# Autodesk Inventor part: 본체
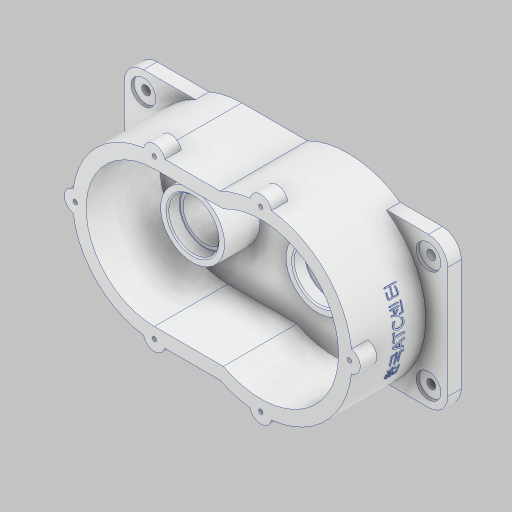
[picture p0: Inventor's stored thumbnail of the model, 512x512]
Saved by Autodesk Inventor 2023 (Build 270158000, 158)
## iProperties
Created: 2025-09
Part Number: 본체
Material: 알루미늄 6061
Document SubType Name: Modeling
Designer: home
Density: 2.7 g/cm^3
Appearance: 알루미늄 - 평지
Mass: 1574.72 g
Surface Area: 1310.46 cm^2
Volume: 583.229 cm^3
Author: home
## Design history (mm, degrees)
sketch "스케치1"
  geometry: L1 (118.5, -55)-(-118.5, -55); L2 (-118.5, -55)-(-118.5, 55); L3 (-118.5, 55)-(118.5, 55); L4 (118.5, 55)-(118.5, -55); L5 (118.5, -55)-(-118.5, 55); L6 (-118.5, -55)-(118.5, 55); 1 further point
  constraints: 12 end point, 2 midpoint, 2 parallel, 1 horizontal, 1 perpendicular
  dimensions: "d0" = 237 distance of L2.end L3.end; "d1" = 110 distance of L1.end L2.end
extrude "돌출1" new body sketch "스케치1" distance "d2" = 10; taper "d3" = 0 deg
fillet "모깎기1" dims "d4" = 14
sketch "스케치2"
  geometry: L1 (-118.5, 41)-(-118.5, -41) reference; L2 (118.5, -41)-(118.5, 41) reference; L3 (104.5, 55)-(-104.5, 55) reference; L4 (-104.5, -55)-(104.5, -55) reference; L5 (-42.5, 66.391)-(-42.5, -77.11); L6 (-118.5, 0)-(118.5, 0); L7 (35.5, 66.391)-(35.5, -81.26); L8 (-42.5, -50)-(8.132, -50); L9 (-42.5, 50)-(8.132, 50); L10 (-42.5, -60)-(5.684, -60); L11 (5.684, 60)-(-42.5, 60); A1 r 50 centre (-42.5, 0) between (-42.5, 50) and (-42.5, -50); A2 r 57 centre (35.5, 0) between (8.132, -50) and (8.132, 50); A3 r 67 centre (35.5, 0) between (5.684, -60) and (5.684, 60); A4 r 60 centre (-42.5, 0) between (-42.5, 60) and (-42.5, -60); 1 further point
  constraints: 14 end point, 8 point on circle, 5 point on line, 4 centre point, 2 midpoint, 2 parallel, 2 tangent, 2 vertical, 1 perpendicular, 3 other
  dimensions: "d5" = 76 distance from line of A1.centre L1; "d6" = 78 distance of A2.centre A1.centre; "d9" = 55 distance from line of L4 A2.centre (derived); "d10" = 57 radius of A2; "d11" = 50 radius of A1; "d12" = 10 radial gap between concentric circles of A1 A4
extrude "돌출2" join sketch "스케치2" distance "d13" = 64; taper "d14" = 0 deg
sketch "스케치3"
  geometry: L1 (-118.5, 41)-(-118.5, -41) reference; L2 (118.5, -41)-(118.5, 41) reference; L3 (-118.5, 0)-(118.5, 0); L4 (-118.5, 58)-(118.5, 58); L5 (-42.5, 0)-(-42.5, -84.517); L6 (-42.5, -60)-(5.684, -60) reference; L7 (-118.5, -58)-(-57.862, -58); L8 (-50.5, -58)-(-34.5, -58); L9 (35.5, 0)-(35.5, -79.976); L10 (27.5, -65)-(43.5, -65); L11 (-50.5, 58)-(-34.5, 58); L12 (27.5, 65)-(43.5, 65); L13 (-100.5, 0)-(-100.5, -84.517); L14 (-100.5, 8)-(-100.5, -8); L15 (0, 0)-(0, -78.559); L16 (100.5, 0)-(100.5, -84.517); L17 (100.5, 8)-(100.5, -8); A1 r 50 centre (-42.5, 0) between (-42.5, 50) and (-42.5, -50) reference; A2 r 57 centre (35.5, 0) between (8.132, -50) and (8.132, 50) reference; A3 r 8 centre (-42.5, -58) between (-50.5, -58) and (-34.5, -58); A4 r 60 centre (-42.5, 0) between (-42.5, 60) and (-42.5, -60) reference; A5 r 57 centre (35.5, 0) between (50.467, -55) and (50.467, 55) reference; A6 r 8 centre (35.5, -65) between (27.5, -65) and (43.5, -65); A7 r 8 centre (-42.5, 58) between (-34.5, 58) and (-50.5, 58); A8 r 8 centre (35.5, 65) between (43.5, 65) and (27.5, 65); A9 r 8 centre (-100.5, 0) between (-100.5, 8) and (-100.5, -8); A10 r 8 centre (100.5, 0) between (100.5, -8) and (100.5, 8); 6 further points
  constraints: 28 end point, 13 point on circle, 11 symmetric about line, 8 midpoint, 6 centre point, 5 parallel, 3 vertical, 2 coincident, 2 point on line, 1 horizontal alignment, 3 other
  dimensions: "d16" = 58 distance between parallel lines of L3 L4; "d17" = 16 diameter of A3; "d21" = 16 diameter of A6; "d22" = 58 distance between parallel lines of L3 L8; "d23" = 65 distance between parallel lines of L3 L10; "d24" = 58 distance between parallel lines of L5 L13; "d25" = 16 diameter of A9; "d26" = 58 distance between parallel lines of L5 L14
extrude "돌출3" join sketch "스케치3" distance "d18" = 12; taper "d19" = 0 deg
sketch "스케치4"
  geometry: L1 (-42.5, 50)-(8.132, 50) reference; L2 (8.132, -50)-(-42.5, -50) reference; C1 r 23.5 at (-42.5, 0); A1 r 50 centre (-42.5, 0) between (-42.5, 50) and (-42.5, -50) reference; A2 r 57 centre (35.5, 0) between (8.132, -50) and (8.132, 50) reference; 1 further point
  constraints: 1 centre point, 1 coincident
  dimensions: "d27" = 47 diameter of C1
extrude "돌출4" join sketch "스케치4" distance "d29" = 26; taper "d30" = 0 deg
sketch "스케치5"
  geometry: C1 r 23.5 at (35.5, 0); A1 r 57 centre (35.5, 0) between (8.132, -50) and (8.132, 50) reference; 1 further point
  constraints: 1 centre point, 1 coincident
  dimensions: "d31" = 47 diameter of C1
extrude "돌출5" join sketch "스케치5" distance "d32" = 12; taper "d33" = 0 deg
sketch "스케치9"
  geometry: L1 (42.5, 10)-(42.5, 10) reference; L2 (42.5, 10)-(42.5, 64) reference; L3 (42.5, 64)-(42.5, 64) reference; L4 (42.5, 10)-(42.5, 64) reference; L5 (66, 36)-(19, 36) reference; L6 (66, 10)-(66, 36) reference; L7 (19, 10)-(19, 36) reference; L8 (-12, 10)-(-12, 22) reference; L9 (-12, 22)-(-59, 22) reference; L10 (-59, 10)-(-59, 22) reference; L11 (42.5, 42.623)-(42.5, -26.9); L12 (61, 36)-(61, 27); L13 (56.5, 11)-(56.5, 8); L14 (56.5, 8)-(42.5, 8); L15 (61, 27)-(58.5, 27); L16 (58.5, 27)-(58.5, 11); L17 (56.5, 11)-(58.5, 11); L18 (61, 36)-(42.5, 36); 5 further points
  constraints: 16 end point, 5 point on line, 3 midpoint, 2 horizontal, 2 perpendicular, 1 vertical
  dimensions: "d42" = 37 diameter of L12 L11; "d44" = 28 diameter of L13 L11; "d45" = 32 diameter of L16 L11; "d46" = 9 distance from line of point (59.75, 27) L5; "d47" = 16 distance of L15.end L16.end; "d48" = 3 distance from line of L14 point (57.5, 11)
revolve "회전1" sketch "스케치9" stored, may be unused: angle "d49" = 360 deg
sketch "스케치10"
  geometry: L1 (-12, 10)-(-12, 22) reference; L2 (-59, 10)-(-59, 22) reference; L3 (-35.5, 22)-(-35.5, -8.141); L4 (-12, 22)-(-59, 22) reference; L5 (-17, 22)-(-17, 13); L6 (-17, 13)-(-20.5, 13); L7 (-20.5, 13)-(-20.5, 8.3); L8 (-20.5, 8.3)-(-18, 8.3); L9 (-5.684, 0)-(-73.762, 0) reference; L10 (-18, 8.3)-(-18, 0); L11 (-18, 0)-(-35.5, 0); L12 (-50.467, 0)-(-20.533, 0) reference; L13 (-17, 22)-(-35.5, 22); 2 further points
  constraints: 16 end point, 4 perpendicular, 2 midpoint, 2 point on line, 2 vertical, 1 collinear
  dimensions: "d51" = 37 diameter of L5 L3; "d52" = 35 diameter of L10 L3; "d53" = 30 diameter of L7 L3; "d54" = 9 distance between parallel lines of L4 L6; "d55" = 8.3 distance between parallel lines of L9 L8
revolve "회전2" sketch "스케치10" stored, may be unused: angle "d56" = 360 deg
fillet "모깎기2" dims "d57" = 0.3
chamfer "모따기1" distance "d58" = 1; stored, may be unused: second distance "d59" = 2, angle "d60" = 45 deg
fillet "모깎기3" dims "d64" = 0.3
fillet "모깎기4" dims "d65" = 0.3
sketch "스케치11"
  geometry: A1 r 67 centre (35.5, 0) between (102.038, 7.851) and (43.351, 66.538) reference; A2 r 8 centre (35.5, 65) between (43.351, 66.538) and (27.649, 66.538) reference; A3 r 8 centre (-42.5, 58) between (-34.754, 60) and (-50.361, 59.483) reference; A4 r 8 centre (-100.5, 0) between (-101.983, 7.861) and (-101.983, -7.861) reference; A5 r 8 centre (-42.5, -58) between (-50.361, -59.483) and (-34.754, -60) reference; A6 r 8 centre (35.5, -65) between (27.649, -66.538) and (43.351, -66.538) reference; A7 r 8 centre (100.5, 0) between (102.038, -7.851) and (102.038, 7.851) reference; 7 further points
  constraints: 6 coincident
hole "구멍2" sketch "스케치11" at (-42.5, 58), (35.5, 65), (100.5, 0), (35.5, -65), (-42.5, -58), (-100.5, 0) diameter "d66" = 3.242; stored, may be unused: countersink angle "d70" = 90 deg, drill point angle "d72" = 118 deg; dims "d67" = 8, "d68" = 4, "d69" = 2, "d71" = 10
sketch "스케치12"
  geometry: L1 (-66.479, 55)-(-104.5, 55) reference; L2 (-118.5, 41)-(-118.5, -41) reference; L3 (-104.5, -55)-(-66.479, -55) reference; L4 (73.762, -55)-(104.5, -55) reference; L5 (118.5, -41)-(118.5, 41) reference; L6 (104.5, 55)-(73.762, 55) reference; A1 r 14 centre (-104.5, 41) between (-104.5, 55) and (-118.5, 41) reference; A2 r 14 centre (-104.5, -41) between (-118.5, -41) and (-104.5, -55) reference; A3 r 14 centre (104.5, -41) between (104.5, -55) and (118.5, -41) reference; A4 r 14 centre (104.5, 41) between (118.5, 41) and (104.5, 55) reference; 1 further point
chamfer "모따기3" distance "d73" = 1; stored, may be unused: second distance "d74" = 2, angle "d75" = 45 deg
chamfer "모따기4" distance "d76" = 0.8; stored, may be unused: second distance "d77" = 2, angle "d78" = 60 deg
hole "구멍3" sketch "스케치12" diameter "d79" = 6.6; stored, may be unused: countersink angle "d83" = 90 deg, drill point angle "d85" = 0 deg; dims "d80" = 6, "d81" = 18, "d82" = 2, "d84" = 10
sketch "스케치13"
  geometry: L1 (-18.637, -58.923)-(-53.607, -58.923); L2 (-53.607, -58.923)-(-53.607, -49.327); L3 (-53.607, -49.327)-(-18.637, -49.327); L4 (-18.637, -49.327)-(-18.637, -58.923); 2 further points
  constraints: 8 end point, 2 parallel, 1 horizontal, 1 midpoint, 1 perpendicular
  dimensions: "d86" = 49.3274 distance from line of point (0, 0) L3; "d87" = 9.59534 distance between parallel lines of L3 L1; "d88" = 34.96967 distance between parallel lines of L2 L4; "d89" = 18.6369 horizontal distance of point (0, 0) point (-18.637, -54.125)
extrude "돌출6" join sketch "스케치13" distance "d90" = 10; taper "d91" = 0 deg
node "작업 평면1"
sketch "스케치14"
  geometry: L1 (-29.534, 0)-(29.534, 0); L2 (29.534, 0)-(29.534, 60); L3 (29.534, 60)-(-29.534, 60); L4 (-29.534, 60)-(-29.534, 0); L5 (-41, 0)-(41, 0) reference; 3 further points
  constraints: 3 midpoint, 2 other
  dimensions: "d92" = 30 distance from line of L5 point (-29.534, 30)
feature "엠보싱1" sketch "스케치14" dims "d0" = 237, "d1" = 110, "d5" = 76, "d6" = 78, "d9" = 55 (derived), "d10" = 57, "d11" = 50, "d12" = 10, "d93" = 0.5, "d94" = 0
node "솔리드1"
mirror "미러1"
node "투영된 루프1"
feature "A9D066F2-1C7D-4E18-AEED-F7BC21143FA4" dims "d79" = 6.6, "d80" = 6, "d81" = 18, "d82" = 2, "d83" = 90 deg, "d84" = 10, "d85" = 0
other parameters: "d8" = 114, "d15" = 58, "d20" = 65
